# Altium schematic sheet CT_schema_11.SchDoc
size 274 x 160 mm
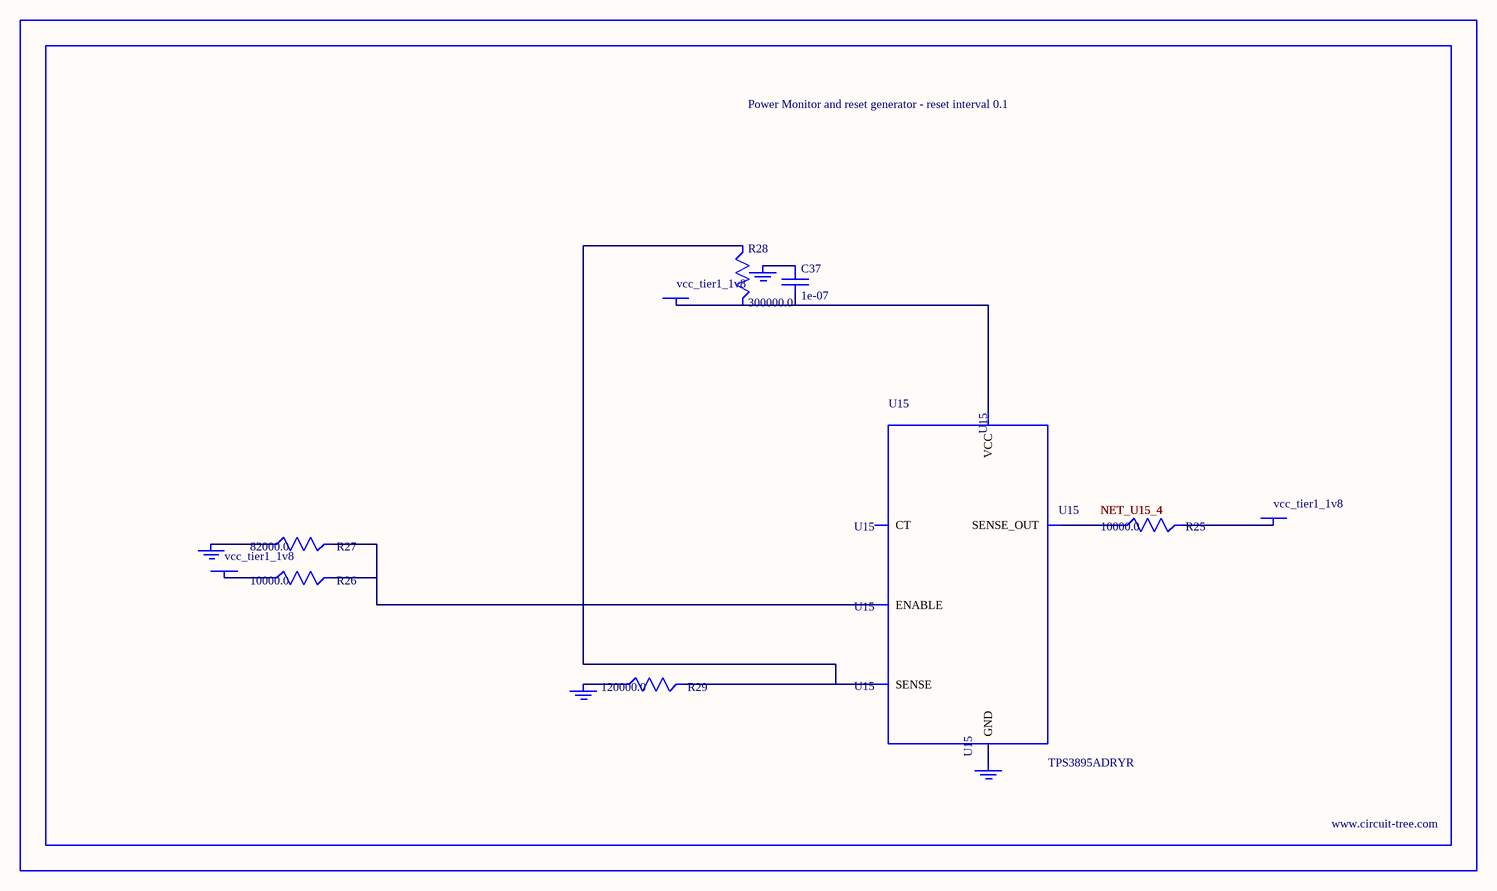
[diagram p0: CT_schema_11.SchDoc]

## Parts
BORDER10  (no value)
C37  1e-07  [C0402]
GND_INSTANCE_10_0  (no value)
GND_INSTANCE_10_1  (no value)
GND_INSTANCE_10_2  (no value)
GND_INSTANCE_10_3  (no value)
POWER_INSTANCE_10_0  vcc_tier1_1v8
POWER_INSTANCE_10_1  vcc_tier1_1v8
POWER_INSTANCE_10_2  vcc_tier1_1v8
R25  10000.0  [R0603]
R26  10000.0  [R0603]
R27  82000.0  [R0603]
R28  300000.0  [R0603]
R29  120000.0  [R0603]
U15  TPS3895ADRYR  [SON-6]

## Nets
NetC37_1: C37.1 GND_INSTANCE_10_2.0(GND)
NetC37_2: C37.2 POWER_INSTANCE_10_2.0(PWR) R28.2 U15.6(VCC)
NetGND_INSTANCE_10_0_0: GND_INSTANCE_10_0.0(GND) R27.1
NetGND_INSTANCE_10_1_0: GND_INSTANCE_10_1.0(GND) R29.1
NetGND_INSTANCE_10_3_0: GND_INSTANCE_10_3.0(GND) U15.2(GND)
NetPOWER_INSTANCE_10_0_0: POWER_INSTANCE_10_0.0(PWR) R26.1
NetPOWER_INSTANCE_10_1_0: POWER_INSTANCE_10_1.0(PWR) R25.2
NetR25_1: R25.1 U15.4(SENSE_OUT)
NetR26_2: R26.2 R27.2 U15.1(ENABLE)
NetR28_1: R28.1 R29.2 U15.3(SENSE)

Not connected (* = marked no-connect by the designer): U15 5(CT)

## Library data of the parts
BORDER10 = BORDER_PAGE10
C37 = C0402C104K3RACTU
GND_INSTANCE_10_0-GND_INSTANCE_10_3 = GND
POWER_INSTANCE_10_0-POWER_INSTANCE_10_2 = PWR
R25 R26 = RC0603JR-0710KL
R27 = RC0603JR-0782KL
R28 = RC0603JR-07300KL
R29 = RC0603JR-07120KL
